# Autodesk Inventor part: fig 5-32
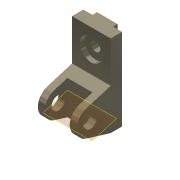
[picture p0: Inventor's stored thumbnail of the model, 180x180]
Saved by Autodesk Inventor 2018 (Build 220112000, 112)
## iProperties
Shininess: 65.0
Angle Display Precision: 2
Document Length Units: 11269
Document Angle Units: 11279
Document Time Units: 11290
Document Mass Units: 11283
Document Length Units Precision: 3
Document Angle Units Precision: 2
Created: 2001-11
Part Number: fig 5-32
Document SubType Name: Modeling
Designer: Renu Muthoo
Density: 1 g/cm^3
Material: Generic
Appearance: Metal-Titanium (Polished)
Density: 0.0
Volumn: 0.0
Area: 0.0
PropertySet Name: Model Information
Control State: 0
Master: False
Checked Out: False
Author: Renu Muthoo
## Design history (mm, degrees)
node "Sketch1"
sketch "Sketch2"
  geometry: L1 (33.257, 104.664)-(33.257, -75.336); L2 (33.257, -75.336)-(8.257, -75.336); L3 (8.257, -75.336)-(-45.451, -59.045); L4 (-45.451, -1.628)-(8.257, 14.664); L5 (8.257, 14.664)-(8.257, 104.664); L6 (8.257, 104.664)-(33.257, 104.664); C1 r 15 at (-36.743, -30.336); A1 r 30 centre (-36.743, -30.336) between (-45.451, -1.628) and (-45.451, -59.045)
  constraints: 12 end point, 2 centre point, 2 equal length, 2 parallel, 2 point on circle, 2 tangent, 1 coincident, 1 perpendicular, 1 vertical
  dimensions: "d0" = 180 distance of L1.start L1.end; "d1" = 30 radius of A1; "d2" = 25 distance of L5.end L1.start; "d3" = 45 distance from line of L2 A1.centre; "d4" = 70 distance from line of L1 A1.centre; "d5" = 30 diameter of C1
extrude "Extrusion1" new body sketch "Sketch2" distance "d6" = 85; taper "d7" = 0 deg
workplane "Work Plane1"
sketch "Sketch3"
  geometry: L1 (15, 62.364)-(70, 62.364); L2 (70, 62.364)-(70, -52.386); L3 (70, -52.386)-(15, -52.386); L4 (15, -52.386)-(15, 62.364); L5 (0, -45)-(0, -28.708) reference
  constraints: 8 end point, 2 parallel, 1 horizontal, 1 perpendicular
  dimensions: "d8" = 55 distance of L1.start L1.end; "d9" = 15 distance between parallel lines of L5 L4
extrude "Extrusion2" cut sketch "Sketch3" distance "d10" = 50; taper "d11" = 0 deg
sketch "Sketch4"
  geometry: L1 (0, 25)-(85, 25) reference; L2 (0, 0)-(0, 25) reference; L3 (20, 25)-(65, 25); L4 (65, 25)-(65, 35); L5 (65, 35)-(20, 35); L6 (20, 35)-(20, 25)
  constraints: 8 end point, 2 parallel, 1 horizontal, 1 perpendicular, 1 point on line
  dimensions: "d12" = 45 distance of L4.end L5.end; "d13" = 10 distance of L3.end L4.end; "d14" = 20 distance between parallel lines of L2 L6
extrude "Extrusion3" join sketch "Sketch4" stored distance "d15" = 50; taper "d16" = 0 deg
sketch "Sketch5"
  geometry: L1 (85, 0)-(85, 90) reference; L2 (0, 90)-(85, 90) reference; 1 further point
  dimensions: "d17" = 42 distance from line of L2 point (42.5, 48); "d18" = 42.5 distance from line of L1 point (42.5, 48)
hole "Hole1" sketch "Sketch5" at (42.5, 48) diameter "d19" = 20; stored, may be unused: countersink angle "d23" = 82 deg, drill point angle "d25" = 118 deg; dims "d20" = 6, "d21" = 50, "d22" = 10, "d24" = 8
workplane "Work Plane6"
body "Solid1"
